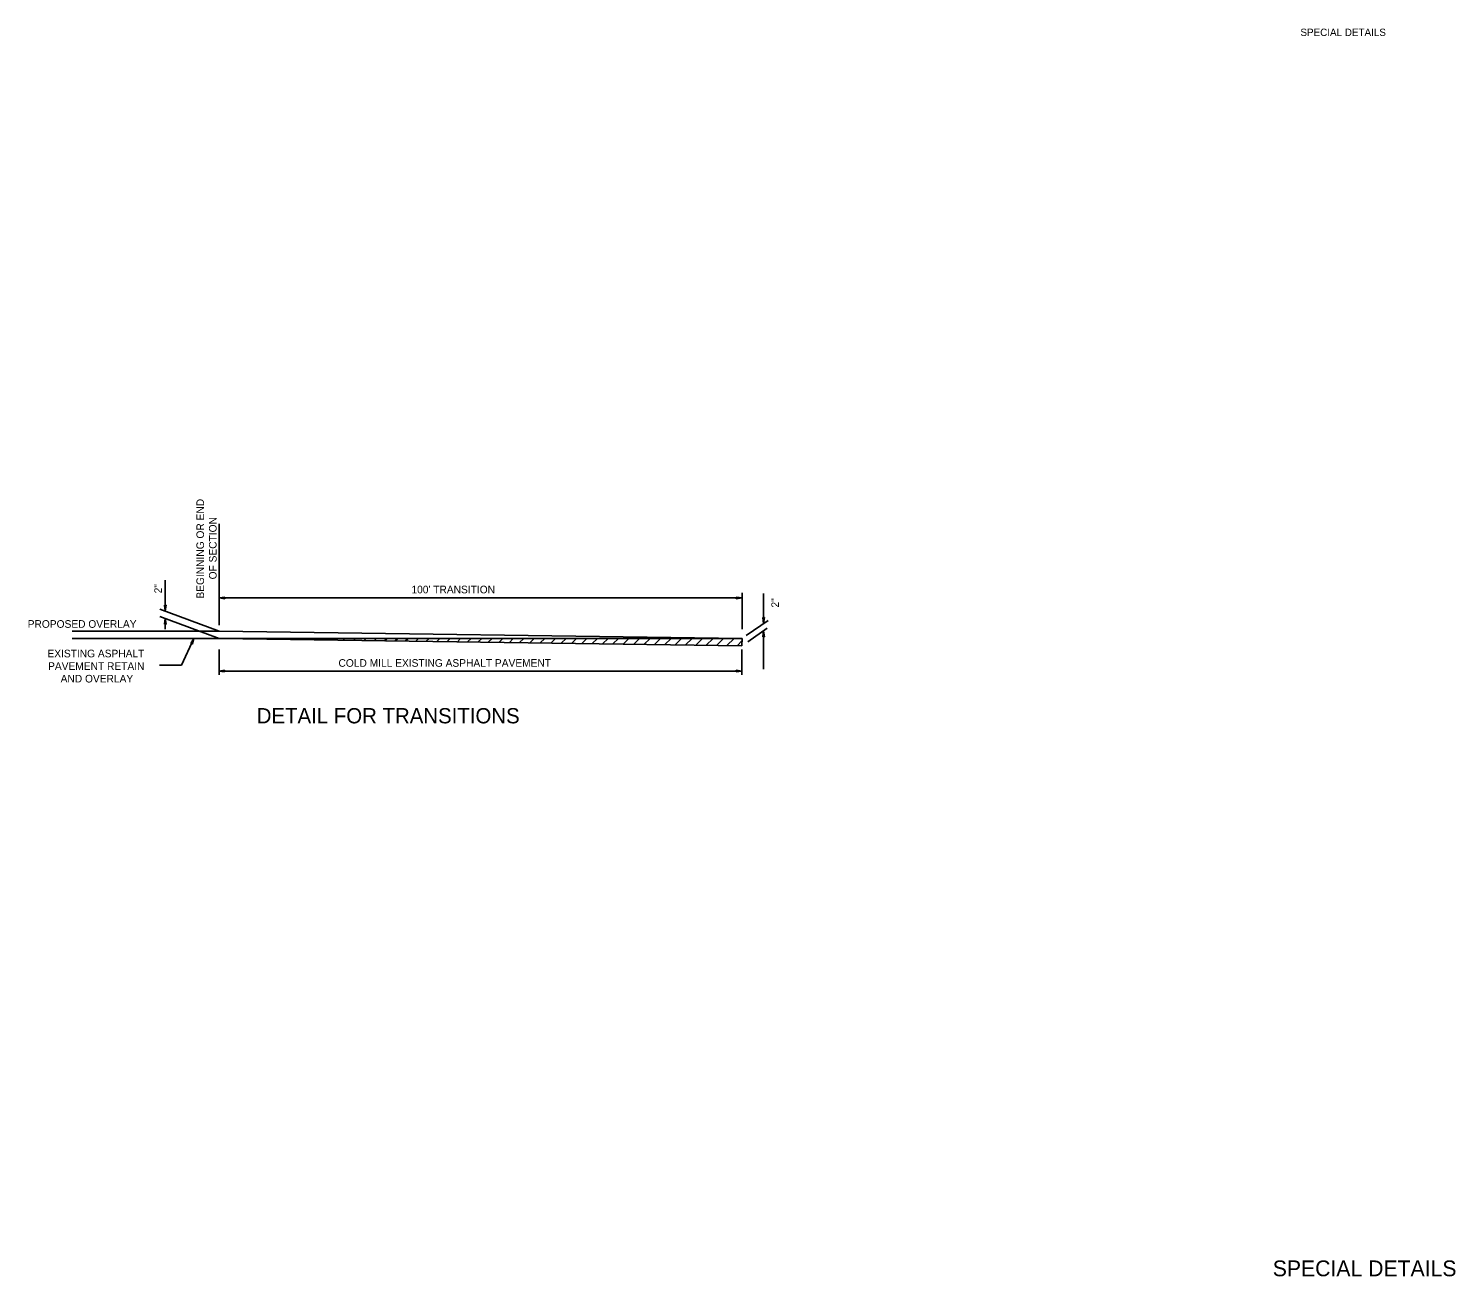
# Model space of a CAD drawing. Extents: x -31606 to 1228740, y -23925 to 152440.
import ezdxf

# ---------------------------------------------------------------- set-up
doc = ezdxf.new("R2010")
doc.units = 0
for name, color, linetype in [('R_Annotation', 7, 'Continuous'), ('R_Border', 7, 'Continuous'), ('R_Dimension', 7, 'Continuous'), ('R_Exist Surface', 7, 'Continuous'), ('R_Proposed Road', 7, 'Continuous'), ('R_Proposed Road_Lane', 7, 'Continuous')]:
    doc.layers.add(name, color=color, linetype=linetype)

msp = doc.modelspace()

# ---------------------------------------------------------------- linework, layer by layer
at = {"layer": 'R_Dimension'}
for p, q in [((-31590.5, -23873.7), (-31590.5, -23865.63)), ((-31594.77, -23872.55), (-31594.77, -23870.13)), ((-31594.84, -23872.1), (-31594.77, -23872.55)), ((-31594.84, -23872.1), (-31594.77, -23872.49)), ((-31594.7, -23872.1), (-31594.84, -23872.1)), ((-31594.81, -23872.1), (-31594.77, -23872.39)), ((-31594.81, -23872.1), (-31594.77, -23872.33)), ((-31594.79, -23872.1), (-31594.77, -23872.24)), ((-31594.79, -23872.1), (-31594.77, -23872.17)), ((-31594.7, -23872.1), (-31594.77, -23872.55)), ((-31594.75, -23872.1), (-31594.77, -23872.24)), ((-31594.72, -23872.1), (-31594.77, -23872.39)), ((-31594.72, -23872.1), (-31594.77, -23872.49)), ((-31594.75, -23872.1), (-31594.77, -23872.33)), ((-31594.77, -23872.1), (-31594.77, -23872.17)), ((-31590.03, -23871.48), (-31590.5, -23871.54)), ((-31590.5, -23871.54), (-31548.91, -23871.54)), ((-31590.03, -23871.61), (-31590.5, -23871.54)), ((-31590.03, -23871.5), (-31590.44, -23871.54)), ((-31590.03, -23871.61), (-31590.44, -23871.54)), ((-31590.03, -23871.5), (-31590.35, -23871.54)), ((-31590.03, -23871.59), (-31590.35, -23871.54)), ((-31590.03, -23871.52), (-31590.26, -23871.54)), ((-31590.03, -23871.59), (-31590.26, -23871.54)), ((-31590.03, -23871.52), (-31590.19, -23871.54)), ((-31590.03, -23871.56), (-31590.19, -23871.54)), ((-31590.03, -23871.54), (-31590.1, -23871.54)), ((-31590.03, -23871.56), (-31590.1, -23871.54)), ((-31590.03, -23871.61), (-31590.03, -23871.48)), ((-31549.38, -23871.48), (-31548.91, -23871.54)), ((-31549.38, -23871.48), (-31549.38, -23871.61)), ((-31549.38, -23871.5), (-31549.06, -23871.54)), ((-31549.38, -23871.5), (-31549, -23871.54)), ((-31549.38, -23871.52), (-31549.22, -23871.54)), ((-31549.38, -23871.52), (-31549.15, -23871.54)), ((-31549.38, -23871.61), (-31548.91, -23871.54)), ((-31549.38, -23871.56), (-31549.22, -23871.54)), ((-31549.38, -23871.59), (-31549.06, -23871.54)), ((-31549.38, -23871.61), (-31549, -23871.54)), ((-31549.38, -23871.59), (-31549.15, -23871.54)), ((-31549.38, -23871.56), (-31549.31, -23871.54)), ((-31549.38, -23871.54), (-31549.31, -23871.54)), ((-31548.91, -23874.01), (-31548.91, -23871.14)), ((-31547.2, -23873.56), (-31547.2, -23871.18)), ((-31590.5, -23874.17), (-31595.2, -23872.42)), ((-31590.5, -23874.75), (-31595.2, -23873)), ((-31594.84, -23873.63), (-31594.77, -23873.16)), ((-31594.84, -23873.63), (-31594.77, -23873.23)), ((-31594.7, -23873.63), (-31594.77, -23873.16)), ((-31594.77, -23874.01), (-31594.77, -23873.16)), ((-31594.72, -23873.63), (-31594.77, -23873.23)), ((-31547.27, -23873.09), (-31547.2, -23873.56)), ((-31547.13, -23873.09), (-31547.27, -23873.09)), ((-31547.25, -23873.09), (-31547.2, -23873.41)), ((-31547.25, -23873.09), (-31547.2, -23873.47)), ((-31547.22, -23873.09), (-31547.2, -23873.25)), ((-31547.22, -23873.09), (-31547.2, -23873.32)), ((-31547.13, -23873.09), (-31547.2, -23873.56)), ((-31547.18, -23873.09), (-31547.2, -23873.25)), ((-31547.16, -23873.09), (-31547.2, -23873.41)), ((-31547.13, -23873.09), (-31547.2, -23873.47)), ((-31547.16, -23873.09), (-31547.2, -23873.32)), ((-31547.2, -23873.09), (-31547.2, -23873.16)), ((-31547.18, -23873.09), (-31547.2, -23873.16)), ((-31594.84, -23873.63), (-31594.7, -23873.63)), ((-31594.81, -23873.63), (-31594.77, -23873.32)), ((-31594.81, -23873.63), (-31594.77, -23873.38)), ((-31594.79, -23873.63), (-31594.77, -23873.47)), ((-31594.79, -23873.63), (-31594.77, -23873.56)), ((-31594.72, -23873.63), (-31594.77, -23873.32)), ((-31594.75, -23873.63), (-31594.77, -23873.38)), ((-31594.75, -23873.63), (-31594.77, -23873.47)), ((-31594.77, -23873.63), (-31594.77, -23873.56)), ((-31548.59, -23874.53), (-31546.84, -23873.32)), ((-31548.46, -23875.02), (-31546.93, -23873.94)), ((-31547.27, -23874.62), (-31547.2, -23874.15)), ((-31547.25, -23874.62), (-31547.2, -23874.21)), ((-31547.25, -23874.62), (-31547.2, -23874.3)), ((-31547.22, -23874.62), (-31547.2, -23874.37)), ((-31547.2, -23877.2), (-31547.2, -23874.15)), ((-31547.13, -23874.62), (-31547.2, -23874.15)), ((-31547.13, -23874.62), (-31547.2, -23874.21)), ((-31547.16, -23874.62), (-31547.2, -23874.3)), ((-31547.16, -23874.62), (-31547.2, -23874.37)), ((-31593.47, -23876.88), (-31592.49, -23874.75)), ((-31592.74, -23875.16), (-31592.49, -23874.75)), ((-31592.74, -23875.16), (-31592.61, -23875.21)), ((-31592.72, -23875.15), (-31592.52, -23874.83)), ((-31592.72, -23875.15), (-31592.56, -23874.9)), ((-31592.71, -23875.17), (-31592.59, -23874.97)), ((-31592.71, -23875.17), (-31592.61, -23875.03)), ((-31592.68, -23875.18), (-31592.65, -23875.11)), ((-31592.68, -23875.18), (-31592.65, -23875.11)), ((-31592.65, -23875.18), (-31592.59, -23874.97)), ((-31592.65, -23875.18), (-31592.61, -23875.03)), ((-31592.64, -23875.21), (-31592.56, -23874.9)), ((-31592.62, -23875.19), (-31592.52, -23874.83)), ((-31592.61, -23875.21), (-31592.49, -23874.75)), ((-31547.27, -23874.62), (-31547.13, -23874.62)), ((-31547.22, -23874.62), (-31547.2, -23874.46)), ((-31547.18, -23874.62), (-31547.2, -23874.46)), ((-31547.18, -23874.62), (-31547.2, -23874.53)), ((-31547.2, -23874.62), (-31547.2, -23874.53)), ((-31590.5, -23877.65), (-31590.5, -23875.63)), ((-31548.93, -23877.65), (-31548.93, -23875.63)), ((-31595.24, -23876.88), (-31593.47, -23876.88)), ((-31590.05, -23877.29), (-31590.5, -23877.36)), ((-31590.05, -23877.29), (-31590.5, -23877.36)), ((-31548.93, -23877.36), (-31590.5, -23877.36)), ((-31590.05, -23877.42), (-31590.5, -23877.36)), ((-31590.05, -23877.42), (-31590.5, -23877.36)), ((-31590.05, -23877.29), (-31590.44, -23877.36)), ((-31590.05, -23877.29), (-31590.44, -23877.36)), ((-31590.05, -23877.4), (-31590.44, -23877.36)), ((-31590.05, -23877.4), (-31590.44, -23877.36)), ((-31590.05, -23877.31), (-31590.35, -23877.36)), ((-31590.05, -23877.31), (-31590.35, -23877.36)), ((-31590.05, -23877.4), (-31590.35, -23877.36)), ((-31590.05, -23877.4), (-31590.35, -23877.36)), ((-31590.05, -23877.31), (-31590.28, -23877.36)), ((-31590.05, -23877.31), (-31590.28, -23877.36)), ((-31590.05, -23877.38), (-31590.28, -23877.36)), ((-31590.05, -23877.38), (-31590.28, -23877.36)), ((-31590.05, -23877.34), (-31590.19, -23877.36)), ((-31590.05, -23877.34), (-31590.19, -23877.36)), ((-31590.05, -23877.38), (-31590.19, -23877.36)), ((-31590.05, -23877.38), (-31590.19, -23877.36)), ((-31590.05, -23877.34), (-31590.12, -23877.36)), ((-31590.05, -23877.34), (-31590.12, -23877.36)), ((-31590.05, -23877.36), (-31590.12, -23877.36)), ((-31590.05, -23877.36), (-31590.12, -23877.36)), ((-31590.05, -23877.42), (-31590.05, -23877.29)), ((-31590.05, -23877.42), (-31590.05, -23877.29)), ((-31549.38, -23877.29), (-31548.93, -23877.36)), ((-31549.38, -23877.29), (-31549, -23877.36)), ((-31549.38, -23877.29), (-31549.38, -23877.42)), ((-31549.38, -23877.31), (-31549.09, -23877.36)), ((-31549.38, -23877.31), (-31549.15, -23877.36)), ((-31549.38, -23877.34), (-31549.24, -23877.36)), ((-31549.38, -23877.34), (-31549.31, -23877.36)), ((-31549.38, -23877.42), (-31548.93, -23877.36)), ((-31549.38, -23877.38), (-31549.24, -23877.36)), ((-31549.38, -23877.4), (-31549.09, -23877.36)), ((-31549.38, -23877.4), (-31549, -23877.36)), ((-31549.38, -23877.38), (-31549.15, -23877.36)), ((-31549.38, -23877.36), (-31549.31, -23877.36))]:
    msp.add_line(p, q, dxfattribs=at)
at = {"layer": 'R_Exist Surface'}
for p, q in [((-31602.18, -23874.75), (-31548.91, -23874.75)), ((-31548.93, -23875.34), (-31590.5, -23874.75))]:
    msp.add_line(p, q, dxfattribs=at)
at = {"layer": 'R_Proposed Road'}
for p, q in [((-31588.87, -23874.78), (-31588.84, -23874.75)), ((-31588.05, -23874.79), (-31588.01, -23874.75)), ((-31587.23, -23874.8), (-31587.16, -23874.75)), ((-31586.39, -23874.81), (-31586.33, -23874.75)), ((-31585.57, -23874.82), (-31585.5, -23874.75)), ((-31584.75, -23874.83), (-31584.67, -23874.75)), ((-31583.93, -23874.84), (-31583.84, -23874.75)), ((-31583.09, -23874.86), (-31582.98, -23874.75)), ((-31582.27, -23874.87), (-31582.15, -23874.75)), ((-31581.43, -23874.88), (-31581.32, -23874.75)), ((-31580.63, -23874.89), (-31580.49, -23874.75)), ((-31579.79, -23874.9), (-31579.64, -23874.75)), ((-31578.97, -23874.91), (-31578.81, -23874.75)), ((-31578.13, -23874.93), (-31577.98, -23874.75)), ((-31577.33, -23874.94), (-31577.12, -23874.75)), ((-31576.49, -23874.95), (-31576.29, -23874.75)), ((-31575.67, -23874.96), (-31575.46, -23874.75)), ((-31574.85, -23874.97), (-31574.63, -23874.75)), ((-31574.03, -23874.98), (-31573.78, -23874.75)), ((-31573.19, -23875), (-31572.95, -23874.75)), ((-31572.37, -23875.01), (-31572.12, -23874.75)), ((-31571.55, -23875.02), (-31571.29, -23874.75)), ((-31570.74, -23875.03), (-31570.44, -23874.75)), ((-31569.89, -23875.04), (-31569.61, -23874.75)), ((-31569.1, -23875.05), (-31568.77, -23874.75)), ((-31568.26, -23875.07), (-31567.94, -23874.75)), ((-31567.41, -23875.08), (-31567.11, -23874.75)), ((-31566.6, -23875.09), (-31566.26, -23874.75)), ((-31565.78, -23875.1), (-31565.43, -23874.75)), ((-31564.96, -23875.11), (-31564.6, -23874.75)), ((-31564.11, -23875.12), (-31563.74, -23874.75)), ((-31563.3, -23875.13), (-31562.91, -23874.75)), ((-31562.48, -23875.15), (-31562.08, -23874.75)), ((-31561.66, -23875.16), (-31561.25, -23874.75)), ((-31560.82, -23875.17), (-31560.4, -23874.75)), ((-31560.02, -23875.18), (-31559.57, -23874.75)), ((-31559.18, -23875.19), (-31558.74, -23874.75)), ((-31558.36, -23875.2), (-31557.91, -23874.75)), ((-31557.52, -23875.22), (-31557.08, -23874.75)), ((-31556.72, -23875.23), (-31556.22, -23874.75)), ((-31555.88, -23875.24), (-31555.39, -23874.75)), ((-31555.06, -23875.25), (-31554.56, -23874.75)), ((-31554.24, -23875.26), (-31553.73, -23874.75)), ((-31553.42, -23875.27), (-31552.88, -23874.75)), ((-31552.58, -23875.29), (-31552.05, -23874.75)), ((-31551.76, -23875.3), (-31551.22, -23874.75)), ((-31550.94, -23875.31), (-31550.39, -23874.75)), ((-31550.13, -23875.32), (-31549.54, -23874.75)), ((-31549.28, -23875.33), (-31548.92, -23874.96)), ((-31548.91, -23874.75), (-31548.93, -23875.34))]:
    msp.add_line(p, q, dxfattribs=at)
at = {"layer": 'R_Proposed Road_Lane'}
for p in [(-31602.18, -23874.17), (-31548.91, -23874.75)]:
    msp.add_line(p, (-31590.5, -23874.17), dxfattribs=at)

# ---------------------------------------------------------------- texts
at = {"layer": 'R_Annotation'}
for s, height, p in [('BEGINNING OR END', 0.6065, (-31591.69, -23871.59)), ('OF SECTION', 0.606, (-31590.69, -23870.06)), ('2"', 0.606, (-31595.04, -23871.17)), ('2"', 0.606, (-31545.98, -23872.3))]:
    msp.add_text(s, height=height, rotation=90, dxfattribs=at).set_placement(p)
for s, height, p in [("100' TRANSITION", 0.6065, (-31575.2, -23871.17)), ('PROPOSED OVERLAY', 0.6065, (-31605.71, -23873.91)), ('EXISTING ASPHALT', 0.6065, (-31604.14, -23876.26)), ('PAVEMENT RETAIN', 0.6065, (-31604.09, -23877.26)), ('COLD MILL EXISTING ASPHALT PAVEMENT', 0.6065, (-31581, -23877.01)), ('AND OVERLAY', 0.6065, (-31603.09, -23878.26)), ('DETAIL FOR TRANSITIONS', 1.2129, (-31587.5, -23881.51))]:
    msp.add_text(s, height=height, dxfattribs=at).set_placement(p)
at = {"layer": 'R_Border'}
for height, p in [(0.5862, (-31504.52, -23826.85)), (1.26, (-31506.72, -23925.48))]:
    msp.add_text('SPECIAL DETAILS', height=height, dxfattribs=at).set_placement(p)

doc.saveas('drawing.dxf')
